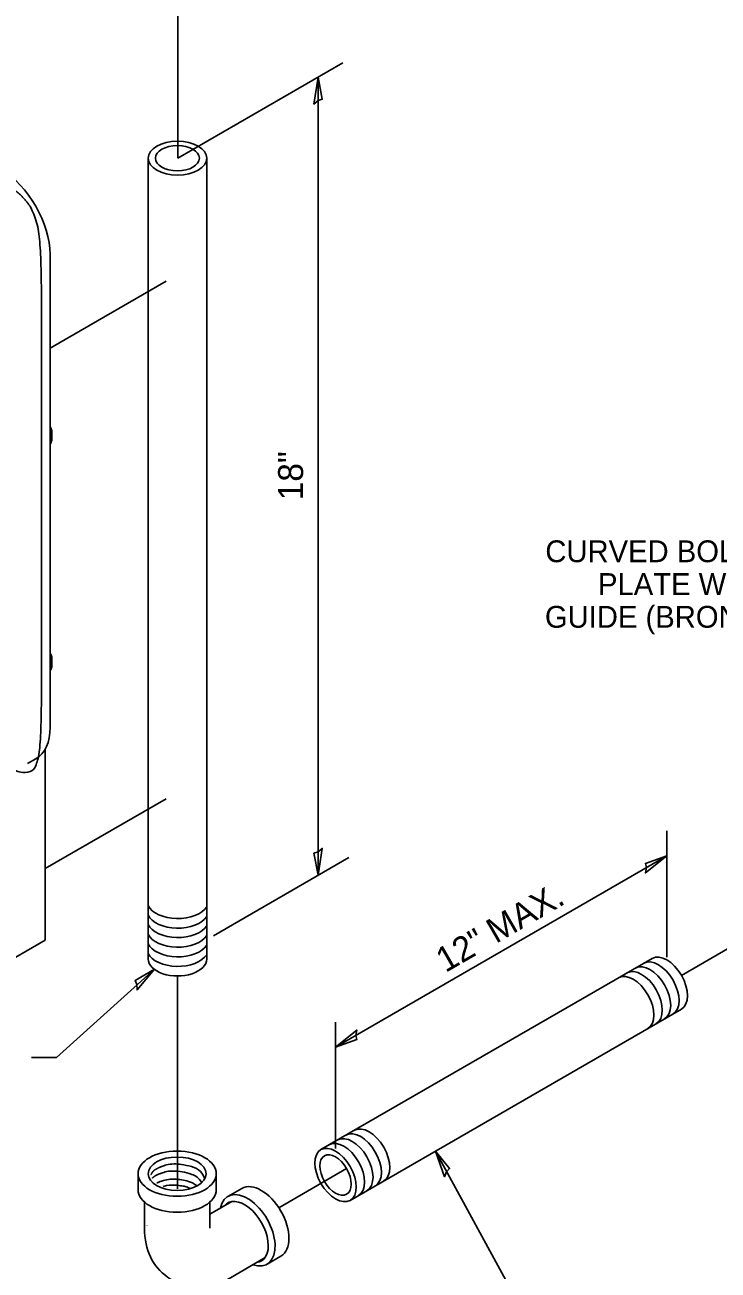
# Model space of a CAD drawing. Extents: x 99999.1 to 100016.1, y 99999.7 to 100010.7.
# Drawn here: x 100009.953 to 100012.175, y 100003.419 to 100007.409 of the extents above; entities that cross this region are included whole.
import ezdxf

# ---------------------------------------------------------------- set-up
doc = ezdxf.new("R2010")
doc.units = 0
for name, color, linetype in [('Level 15', 7, 'Continuous'), ('Level 2', 7, 'Continuous'), ('Level 20', 7, 'Continuous'), ('Level 3', 7, 'Continuous'), ('Level 33', 7, 'Continuous'), ('Level 40', 7, 'Continuous'), ('Level 41', 7, 'Continuous'), ('Level 5', 7, 'Continuous')]:
    doc.layers.add(name, color=color, linetype=linetype)

msp = doc.modelspace()

# ---------------------------------------------------------------- linework, layer by layer
at = {"layer": 'Level 15'}
for p, q in [((100010.443, 100007.543), (100010.443, 100006.9819)), ((100010.443, 100006.9819), (100010.9726, 100007.2877)), ((100010.8932, 100004.6838), (100010.8932, 100007.2418)), ((100010.0342, 100006.3732), (100010.4061, 100006.5879)), ((100010.0185, 100004.7055), (100010.4061, 100004.9293)), ((100012.9536, 100004.8809), (100012.0572, 100004.3633)), ((100012.0103, 100004.4213), (100012.0103, 100004.8261)), ((100012.0103, 100004.7461), (100010.9489, 100004.1334)), ((100010.5574, 100004.4899), (100010.9919, 100004.7408)), ((100010.3686, 100004.3836), (100010.0544, 100004.0998)), ((100010.4426, 100004.3614), (100010.4426, 100003.679)), ((100010.9489, 100003.8085), (100010.9489, 100004.2134)), ((100009.9744, 100004.0998), (100010.0544, 100004.0998)), ((100011.5333, 100003.3165), (100011.269, 100003.8001)), ((100010.9845, 100003.744), (100010.7671, 100003.6185))]:
    msp.add_line(p, q, dxfattribs=at)
for points in [[(100010.8932, 100007.2418), (100010.9065, 100007.1709), (100010.8932, 100007.1668), (100010.8798, 100007.1555)], [(100010.8932, 100004.6838), (100010.9065, 100004.7701), (100010.8932, 100004.7588), (100010.8798, 100004.7547)], [(100012.0103, 100004.7461), (100011.9422, 100004.6914), (100011.9453, 100004.7086), (100011.9422, 100004.7222)], [(100010.3686, 100004.3836), (100010.3126, 100004.3165), (100010.3123, 100004.334), (100010.3065, 100004.3467)], [(100010.9489, 100004.1334), (100011.017, 100004.1881), (100011.0139, 100004.1709), (100011.017, 100004.1573)], [(100011.269, 100003.8001), (100011.3144, 100003.7439), (100011.3045, 100003.734), (100011.2982, 100003.7177)]]:
    msp.add_lwpolyline(points, close=True, dxfattribs=at)
at = {"layer": 'Level 2'}
for p, q in [((100010.3159, 100003.7277), (100010.3159, 100003.6765)), ((100010.5667, 100003.6765), (100010.5667, 100003.7277)), ((100010.6482, 100003.6805), (100010.6039, 100003.6549)), ((100010.7292, 100003.4377), (100010.7736, 100003.4633))]:
    msp.add_line(p, q, dxfattribs=at)
msp.add_ellipse((100010.4413, 100003.7275), major_axis=(0.093, 0), ratio=0.57735, dxfattribs=at)
for centre, major_axis, start_param, end_param in [((100010.4413, 100003.6765), (0.1254, 0), 3.141593, 6.283185), ((100010.7109, 100003.5719), (-0.0627, 0.1086), 3.141593, 6.283185), ((100010.6571, 100003.5408), (-0.0538, 0.0932), 2.881416, 6.510274)]:
    msp.add_ellipse(centre, major_axis=major_axis, ratio=0.57735, start_param=start_param, end_param=end_param, dxfattribs=at)
for points, degree in [([(100010.5292, 100003.7107), (100010.529, 100003.7118), (100010.5241, 100003.7315), (100010.497, 100003.7497), (100010.4608, 100003.7564), (100010.4369, 100003.7599), (100010.4117, 100003.7576), (100010.3933, 100003.7515), (100010.3901, 100003.7503), (100010.3871, 100003.7491), (100010.3842, 100003.7478), (100010.3823, 100003.7469), (100010.3814, 100003.7464)], 3), ([(100010.3814, 100003.7464), (100010.3701, 100003.7407), (100010.3618, 100003.7331), (100010.3573, 100003.7247)], 2), ([(100010.3768, 100003.7238), (100010.371, 100003.7209), (100010.3659, 100003.7174), (100010.3618, 100003.7136)], 2), ([(100010.5048, 100003.6888), (100010.4937, 100003.6969), (100010.4777, 100003.7038), (100010.4557, 100003.7079), (100010.4318, 100003.7114), (100010.4066, 100003.7091), (100010.3882, 100003.703), (100010.385, 100003.7018), (100010.382, 100003.7006), (100010.3791, 100003.6993), (100010.3772, 100003.6984), (100010.3763, 100003.6979)], 3), ([(100010.5202, 100003.6992), (100010.5108, 100003.7145), (100010.488, 100003.728), (100010.4563, 100003.7338), (100010.4324, 100003.7373), (100010.4072, 100003.735), (100010.3888, 100003.7289), (100010.3856, 100003.7278), (100010.3825, 100003.7265), (100010.3796, 100003.7252), (100010.3777, 100003.7243), (100010.3768, 100003.7238)], 3), ([(100010.483, 100003.681), (100010.4759, 100003.6839), (100010.4669, 100003.6867), (100010.4537, 100003.6892), (100010.4323, 100003.6922), (100010.4113, 100003.6909), (100010.3963, 100003.6872)], 3)]:
    msp.add_open_spline(points, degree=degree, dxfattribs=at)
at = {"layer": 'Level 3'}
for p, q in [((100010.3485, 100006.9819), (100010.3485, 100004.4155)), ((100010.5359, 100004.4155), (100010.5359, 100006.9819)), ((100011.9634, 100004.4175), (100010.9021, 100003.8047)), ((100010.9958, 100003.6423), (100012.0572, 100004.2551))]:
    msp.add_line(p, q, dxfattribs=at)
for centre, major_axis in [((100010.4422, 100006.9819), (0.0937, 0)), ((100010.4422, 100006.9819), (0.0703, 0)), ((100010.9489, 100003.7235), (-0.0469, 0.0812)), ((100010.9489, 100003.7235), (0.0356, -0.0616))]:
    msp.add_ellipse(centre, major_axis=major_axis, ratio=0.57735, dxfattribs=at)
for centre, major_axis, start_param, end_param in [((100010.4433, 100004.6019), (0.0984, 0), 3.411426, 5.937805), ((100010.4433, 100004.5713), (0.0984, 0), 2.86885, 2.871759), ((100010.4433, 100004.5713), (0.0984, 0), 3.411426, 5.937805), ((100010.4433, 100004.5413), (0.0984, 0), 3.411426, 5.937805), ((100010.4433, 100004.5101), (0.0984, 0), 2.86338, 2.871759), ((100010.4433, 100004.5101), (0.0984, 0), 3.411426, 5.937805), ((100010.4433, 100004.4795), (0.0984, 0), 2.86885, 2.871759), ((100010.4433, 100004.4795), (0.0984, 0), 3.411426, 5.937805), ((100010.4433, 100004.4488), (0.0984, 0), 2.86885, 2.871759), ((100010.4433, 100004.4488), (0.0984, 0), 3.411426, 5.937805), ((100012.0103, 100004.3363), (-0.0469, 0.0812), 3.141593, 6.283185), ((100010.4422, 100004.4155), (-0.0937, 0), 0, 3.141593), ((100011.9566, 100004.3053), (-0.0469, 0.0812), 3.141593, 6.283185), ((100011.9835, 100004.3208), (-0.0469, 0.0812), 3.141593, 6.283185), ((100011.9029, 100004.2743), (-0.0469, 0.0812), 3.141593, 6.283185), ((100011.9298, 100004.2898), (-0.0469, 0.0812), 3.141593, 6.283185), ((100011.0563, 100003.7855), (-0.0469, 0.0812), 3.141593, 6.283185), ((100010.9758, 100003.739), (-0.0469, 0.0812), 3.141593, 6.283185), ((100011.0026, 100003.7545), (-0.0469, 0.0812), 3.141593, 6.283185), ((100011.0295, 100003.77), (-0.0469, 0.0812), 3.141593, 6.283185)]:
    msp.add_ellipse(centre, major_axis=major_axis, ratio=0.57735, start_param=start_param, end_param=end_param, dxfattribs=at)
at = {"layer": 'Level 33'}
for p, q in [((100010.0391, 100006.078), (100010.0391, 100006.1083)), ((100010.0391, 100005.3522), (100010.0391, 100005.3825)), ((100010.0185, 100005.0887), (100010.0185, 100004.4756)), ((100010.0185, 100004.4756), (100009.8587, 100004.3834))]:
    msp.add_line(p, q, dxfattribs=at)
for centre, start, end in [((100010.0206, 100006.1083), 0, 42.493), ((100010.0206, 100006.078), 317.507, 0), ((100010.0206, 100005.3825), 0, 42.493), ((100010.0206, 100005.3522), 317.507, 0)]:
    msp.add_arc(centre, 0.0185, start, end, dxfattribs=at)
for centre in [(100010.0206, 100006.1083), (100010.0206, 100006.078)]:
    msp.add_ellipse(centre, major_axis=(0.0185, 0), ratio=0.57735, start_param=5.541543, end_param=6.283185, dxfattribs=at)
at = {"layer": 'Level 40'}
msp.add_open_spline([(100009.1108, 100007.3039), (100009.1567, 100007.3296), (100009.2211, 100007.2924), (100009.5353, 100007.1109), (100009.8496, 100006.9295), (100010.0067, 100006.8388), (100010.0067, 100006.6573), (100010.0067, 100005.9001), (100010.0067, 100005.1429), (100010.0067, 100004.9614), (100009.8496, 100005.0522), (100009.5353, 100005.2336), (100009.2211, 100005.4151), (100009.2121, 100005.4202), (100009.2033, 100005.4265)], degree=4, dxfattribs=at)
at = {"layer": 'Level 41'}
for p, q in [((100010.0342, 100006.6732), (100010.0342, 100005.1588)), ((100009.962, 100005.0419), (100009.9882, 100005.057))]:
    msp.add_line(p, q, dxfattribs=at)
for centre, major_axis, start_param, end_param in [((100009.8771, 100006.7639), (-0.1111, 0.1925), 3.926991, 5.497787), ((100009.8771, 100005.2495), (0.1111, -0.1925), 6.283185, 7.068583)]:
    msp.add_ellipse(centre, major_axis=major_axis, ratio=0.57735, start_param=start_param, end_param=end_param, dxfattribs=at)
at = {"layer": 'Level 5'}
for p, q in [((100010.3368, 100003.6365), (100010.3368, 100003.5532)), ((100010.6167, 100003.6387), (100010.5458, 100003.5977)), ((100010.5458, 100003.5532), (100010.5458, 100003.6365)), ((100010.6117, 100003.3945), (100010.7229, 100003.4587))]:
    msp.add_line(p, q, dxfattribs=at)
for centre, major_axis in [((100010.4413, 100003.7277), (0.1254, 0)), ((100010.4413, 100003.7275), (0.093, 0))]:
    msp.add_ellipse(centre, major_axis=major_axis, ratio=0.57735, dxfattribs=at)
for centre, major_axis, start_param, end_param in [((100010.6666, 100003.5463), (-0.0627, 0.1086), 2.549736, 6.862641), ((100010.4414, 100003.5629), (-0.0965, 0), 6.283185, 6.283255)]:
    msp.add_ellipse(centre, major_axis=major_axis, ratio=0.57735, start_param=start_param, end_param=end_param, dxfattribs=at)
msp.add_open_spline([(100010.3368, 100003.5532), (100010.3368, 100003.517), (100010.3496, 100003.4571), (100010.4045, 100003.3923), (100010.4947, 100003.3525), (100010.5687, 100003.3697), (100010.6117, 100003.3945)], degree=3, dxfattribs=at)

# ---------------------------------------------------------------- texts
at = {"layer": 'Level 20'}
for s, rotation, p in [('18"', 90, (100010.8448, 100005.8858)), ('12" MAX.', 30, (100011.3011, 100004.3705))]:
    msp.add_text(s, height=0.08, rotation=rotation, dxfattribs=at).set_placement(p)
for s, p in [('CURVED BOLT-ON HUB', (100011.6212, 100005.6872)), ('PLATE WITH CABLE', (100011.7901, 100005.5822)), ('GUIDE (BRONZE) (TYP.)', (100011.6199, 100005.4772))]:
    msp.add_text(s, height=0.07, dxfattribs=at).set_placement(p)

doc.saveas('drawing.dxf')
